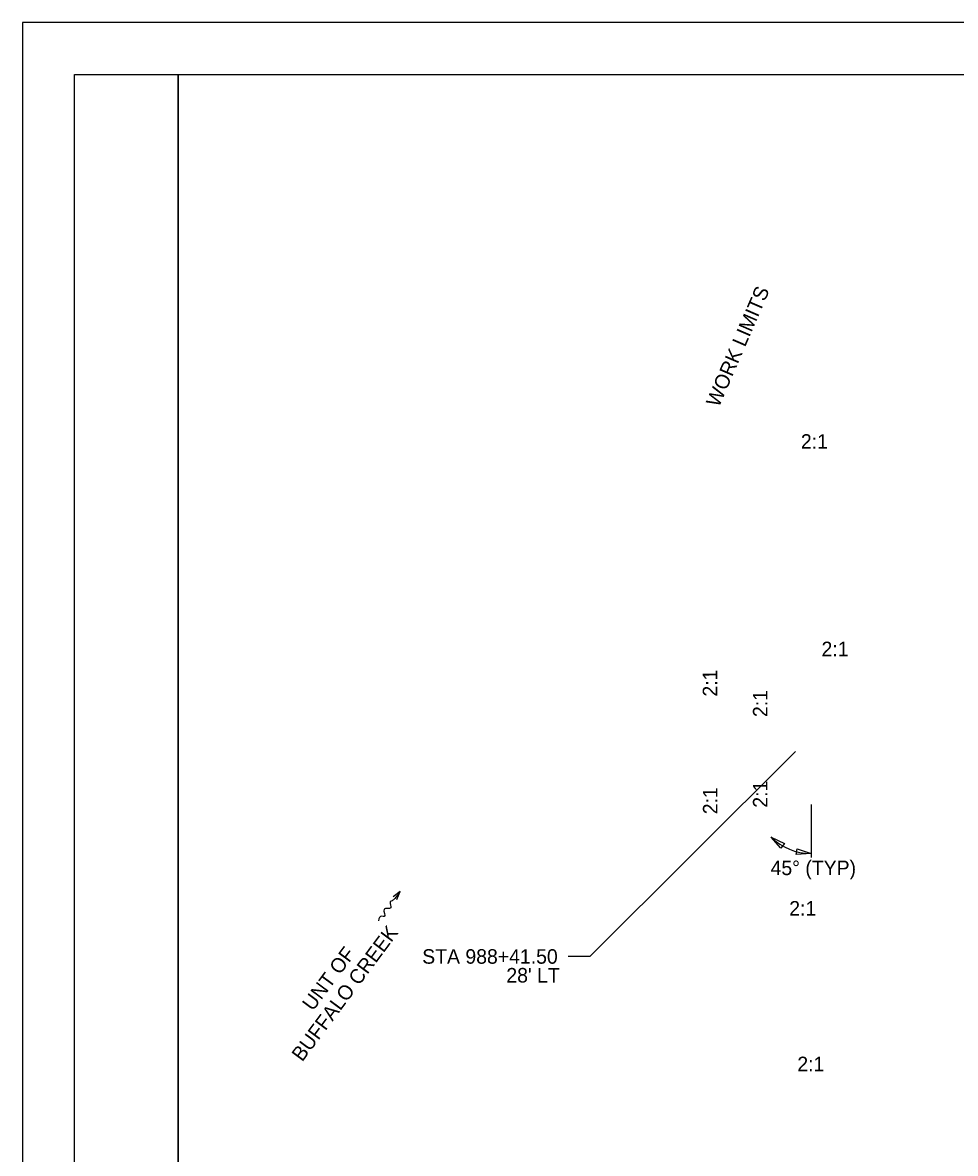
# Model space of a CAD drawing. Extents: x 0 to 486, y 0 to 220.
# Drawn here: x 0 to 89.9, y 111 to 220 of the extents above; entities that cross this region are included whole.
import ezdxf

# ---------------------------------------------------------------- set-up
doc = ezdxf.new("R2010")
doc.units = 0
for name, color, linetype in [('DR_P_Culvert', 7, 'Continuous'), ('DR_X_Culvert', 7, 'Continuous'), ('DT_P_Slope_Break_Line', 7, 'Continuous'), ('GE_X_Alignment', 7, 'Continuous'), ('GE_X_Alignment_100_Cardinal_Points', 7, 'Continuous'), ('PF_X_Ground_Line', 7, 'Continuous'), ('SC_Scratch1', 7, 'Continuous')]:
    doc.layers.add(name, color=color, linetype=linetype)

msp = doc.modelspace()

# ---------------------------------------------------------------- linework, layer by layer
at = {"layer": 'DR_X_Culvert'}
msp.add_lwpolyline([(0, 0), (340, 0), (340, 220), (0, 220)], close=True, dxfattribs=at)
at = {"layer": 'DT_P_Slope_Break_Line'}
for p, q in [((36.38, 136.25), (35.73, 135.73)), ((36.07, 135.48), (36.38, 136.25))]:
    msp.add_line(p, q, dxfattribs=at)
msp.add_spline([(36.38, 136.25), (35.88, 135.58), (35.62, 135.36), (35.44, 135.24), (35.48, 134.68), (34.86, 134.54), (34.86, 133.84), (34.61, 133.88), (34.29, 133.44)], degree=3, dxfattribs=at)
at = {"layer": 'GE_X_Alignment'}
for points in [[(73.43, 140.87), (73.09, 140.43), (72.15, 141.5)], [(74.58, 139.81), (74.65, 140.37), (76, 139.91)]]:
    msp.add_lwpolyline(points, close=True, dxfattribs=at)
at = {"layer": 'GE_X_Alignment_100_Cardinal_Points'}
for p, q in [((54.69, 129.99), (74.5, 149.73)), ((76, 144.63), (76, 139.53))]:
    msp.add_line(p, q, dxfattribs=at)
msp.add_arc((76, 145.36), 5.45, 225, 270, dxfattribs=at)
at = {"layer": 'PF_X_Ground_Line'}
for points in [[(5, 215), (15, 215), (15, 5), (5, 5)], [(15, 215), (335, 215), (335, 5), (15, 5)]]:
    msp.add_lwpolyline(points, close=True, dxfattribs=at)
at = {"layer": 'SC_Scratch1'}
msp.add_line((54.69, 129.99), (52.58, 129.99), dxfattribs=at)

# ---------------------------------------------------------------- texts
at = {"layer": 'DR_P_Culvert'}
for s, p in [('BUFFALO CREEK', (26.95, 119.77)), ('UNT OF', (27.97, 124.65))]:
    msp.add_text(s, height=1.4, rotation=53.3171, dxfattribs=at).set_placement(p)
at = {"layer": 'GE_X_Alignment_100_Cardinal_Points'}
for s, rotation, p in [('WORK LIMITS', 66.5887, (67.11, 182.84)), ('2:1', 360, (75.02, 178.93)), ('2:1', 0, (77.01, 158.93)), ('2:1', 90.0983, (66.96, 155.04)), ('2:1', 90.0983, (71.8, 153.07)), ('2:1', 90.0983, (66.98, 143.7)), ('2:1', 90.0983, (71.8, 144.33)), ('2:1', 0, (74.68, 118.93))]:
    msp.add_text(s, height=1.4, rotation=rotation, dxfattribs=at).set_placement(p)
for s, p in [('45° (TYP)', (72.1, 137.83)), ('2:1', (73.9, 133.93)), ('STA 988+41.50', (38.52, 129.29)), ("28' LT", (46.63, 127.48))]:
    msp.add_text(s, height=1.4, dxfattribs=at).set_placement(p)

doc.saveas('drawing.dxf')
